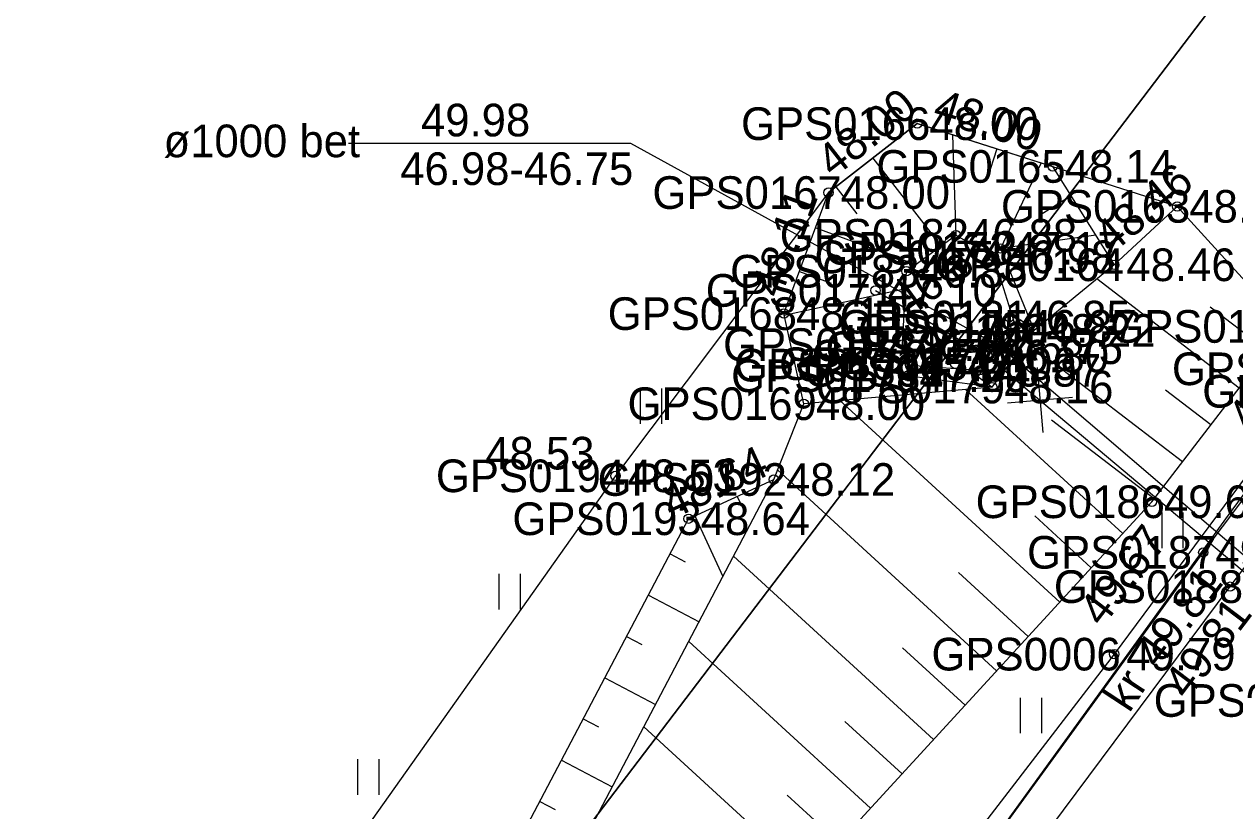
# Model space of a CAD drawing. Extents: x 563121 to 567545, y 6570841 to 6581299.
# Drawn here: x 565796.21 to 565822.17, y 6571860.9 to 6571877.77 of the extents above; entities that cross this region are included whole.
import ezdxf

# ---------------------------------------------------------------- set-up
doc = ezdxf.new("R2010")
doc.units = 0
for name, color, linetype in [('HALJASTUS', 7, 'Continuous'), ('KORGUS-EH2000', 7, 'Continuous'), ('MOOTKORG-EH2000', 7, 'Continuous'), ('MOOTMPUNKT', 7, 'Continuous'), ('MOOTNR', 7, 'Continuous'), ('MOOTPIIR', 7, 'Continuous'), ('PIIR', 7, 'Continuous'), ('RELJEEF', 7, 'Continuous'), ('SITRASS', 7, 'Continuous'), ('TEE', 7, 'Continuous'), ('TRUUP', 7, 'Continuous')]:
    doc.layers.add(name, color=color, linetype=linetype)

msp = doc.modelspace()

# ---------------------------------------------------------------- linework, layer by layer
at = {"layer": 'HALJASTUS'}
for p, q in [((565809.42, 6571869.956), (565809.42, 6571869.195)), ((565809.875, 6571869.956), (565809.875, 6571869.195)), ((565820.607, 6571867.295), (565820.607, 6571866.533)), ((565821.062, 6571867.295), (565821.062, 6571866.533)), ((565806.389, 6571865.979), (565806.389, 6571865.218)), ((565806.844, 6571865.979), (565806.844, 6571865.218)), ((565817.572, 6571863.321), (565817.572, 6571862.56)), ((565818.027, 6571863.321), (565818.027, 6571862.56)), ((565803.358, 6571862.003), (565803.358, 6571861.242)), ((565803.813, 6571862.003), (565803.813, 6571861.242))]:
    msp.add_line(p, q, dxfattribs=at)
at = {"layer": 'KORGUS-EH2000'}
for centre in [(565815.364, 6571875.639), (565818.268, 6571874.721), (565813.463, 6571874.16), (565819.589, 6571872.611), (565815.131, 6571872.472), (565812.505, 6571871.563), (565808.89, 6571868.083), (565820.396, 6571867.526), (565810.46, 6571867.163), (565821.499, 6571866.441), (565822.074, 6571865.705)]:
    msp.add_circle(centre, 0.1, dxfattribs=at)
at = {"layer": 'MOOTMPUNKT'}
for centre in [(565815.364, 6571875.639), (565818.268, 6571874.721), (565813.463, 6571874.16), (565820.939, 6571873.864), (565816.193, 6571873.244), (565817.007, 6571872.781), (565817.149, 6571872.963), (565819.589, 6571872.611), (565815.131, 6571872.472), (565814.466, 6571872.061), (565812.505, 6571871.563), (565817.339, 6571871.488), (565817.469, 6571871.291), (565817.872, 6571871.202), (565815.049, 6571870.898), (565817.174, 6571870.831), (565815.213, 6571870.458), (565816.178, 6571870.488), (565816.874, 6571870.651), (565815.151, 6571870.23), (565816.705, 6571870.347), (565816.969, 6571869.988), (565812.929, 6571869.63), (565808.89, 6571868.083), (565812.288, 6571868.004), (565820.396, 6571867.526), (565810.46, 6571867.163), (565821.499, 6571866.441), (565822.074, 6571865.705), (565819.589, 6571864.258)]:
    msp.add_circle(centre, 0.1, dxfattribs=at)
at = {"layer": 'MOOTPIIR'}
msp.add_lwpolyline([(565823.283, 6571871.288), (565820.939, 6571873.864), (565815.364, 6571875.639), (565813.463, 6571874.16), (565808.89, 6571868.083), (565802.021, 6571858.377), (565795.67, 6571849.773), (565782.207, 6571833.008), (565776.308, 6571825.832), (565781.278, 6571820.922), (565782.262, 6571820.691), (565783.542, 6571819.443), (565784.347, 6571818.115), (565785.017, 6571817.401), (565789.374, 6571812.429), (565790.175, 6571811.534), (565801.221, 6571799.668)], dxfattribs=at)
at = {"layer": 'PIIR'}
msp.add_lwpolyline([(564959.63, 6571567.88), (565247.22, 6571575.87), (565310, 6571592), (565385.09, 6571617.94), (565603.34, 6571696.36), (565663.71, 6571724.88), (565720.01, 6571762.52), (565767.05, 6571806.3), (565831.51, 6571891.07), (565894.85, 6571978.6), (565929.68, 6572026.82), (566028.25, 6572163.26), (566043.71, 6572184.75), (566068.58, 6572219.3), (566114.67, 6572283.35)], dxfattribs=at)
msp.add_lwpolyline([(565385.09, 6571617.94), (565348.3, 6571706.93), (565808.88, 6572174.3), (565817.95, 6572187.54), (565914.67, 6572223.63), (565927.34, 6572201.79), (566013.66, 6572213.36), (566028.25, 6572163.26), (565929.68, 6572026.82), (565869.35, 6572071.5), (565833.75, 6572019.48), (565773.79, 6571931.89), (565831.51, 6571891.07), (565767.05, 6571806.3), (565720.01, 6571762.52), (565663.71, 6571724.88), (565603.34, 6571696.36)], close=True, dxfattribs=at)
at = {"layer": 'RELJEEF'}
for p, q in [((565816.117, 6571875.401), (565816.193, 6571873.244)), ((565817.07, 6571875.1), (565816.866, 6571874.453)), ((565814.409, 6571874.896), (565815.875, 6571873.013)), ((565818.024, 6571874.798), (565817.149, 6571872.963)), ((565813.62, 6571874.281), (565814.071, 6571873.702)), ((565818.663, 6571874.091), (565818.019, 6571873.688)), ((565819.589, 6571872.611), (565820.939, 6571873.864)), ((565813.186, 6571873.407), (565815.33, 6571872.616)), ((565819.194, 6571873.243), (565817.149, 6571872.963)), ((565812.839, 6571872.469), (565813.514, 6571872.22)), ((565812.512, 6571871.53), (565815.111, 6571872.1)), ((565822.269, 6571869.967), (565819.219, 6571872.307)), ((565822.878, 6571870.76), (565821.648, 6571871.704)), ((565821.051, 6571868.38), (565817.691, 6571870.959)), ((565812.727, 6571870.553), (565813.426, 6571870.707)), ((565815.972, 6571869.899), (565815.954, 6571870.105)), ((565819.772, 6571866.846), (565816.402, 6571869.937)), ((565821.66, 6571869.174), (565820.69, 6571869.918)), ((565818.419, 6571865.372), (565813.704, 6571869.699)), ((565820.442, 6571867.587), (565818.244, 6571869.274)), ((565817.067, 6571863.898), (565812.369, 6571868.209)), ((565811.501, 6571867.642), (565811.584, 6571867.46)), ((565810.593, 6571867.224), (565811.193, 6571865.92)), ((565819.096, 6571866.109), (565817.883, 6571867.222)), ((565810.062, 6571866.407), (565810.388, 6571866.236)), ((565815.715, 6571862.425), (565811.424, 6571866.361)), ((565817.743, 6571864.635), (565816.249, 6571866.006)), ((565809.597, 6571865.522), (565810.683, 6571864.95)), ((565809.131, 6571864.637), (565809.457, 6571864.465)), ((565814.363, 6571860.951), (565810.462, 6571864.53)), ((565816.391, 6571863.162), (565815.046, 6571864.396)), ((565808.666, 6571863.752), (565809.753, 6571863.18)), ((565808.2, 6571862.867), (565808.527, 6571862.695)), ((565815.039, 6571861.688), (565813.81, 6571862.815)), ((565813.011, 6571859.477), (565809.5, 6571862.699)), ((565807.735, 6571861.982), (565808.823, 6571861.409)), ((565813.687, 6571860.214), (565812.575, 6571861.234)), ((565807.269, 6571861.097), (565807.596, 6571860.925))]:
    msp.add_line(p, q, dxfattribs=at)
for points in [[(565816.969, 6571869.988), (565812.929, 6571869.63), (565812.505, 6571871.563), (565813.463, 6571874.16), (565815.364, 6571875.639), (565818.268, 6571874.721), (565819.589, 6571872.611), (565817.872, 6571871.202)], [(565815.213, 6571870.458), (565815.049, 6571870.898), (565815.131, 6571872.472), (565816.193, 6571873.244), (565817.007, 6571872.781)], [(565800.51, 6571847.744), (565800.538, 6571847.723), (565801.66, 6571847.165), (565807.743, 6571853.735), (565820.396, 6571867.526), (565823.283, 6571871.288)], [(565800.861, 6571849.149), (565805.762, 6571855.585), (565812.288, 6571868.004), (565812.929, 6571869.63)], [(565799.345, 6571848.635), (565799.323, 6571848.653), (565799.23, 6571849.388), (565804.852, 6571856.501), (565810.46, 6571867.163), (565812.288, 6571868.004)]]:
    msp.add_lwpolyline(points, dxfattribs=at)
at = {"layer": 'SITRASS'}
for p, q in [((565817.933, 6571870.408), (565818.054, 6571869.013)), ((565817.296, 6571869.65), (565818.691, 6571869.771))]:
    msp.add_line(p, q, dxfattribs=at)
for points in [[(565827.937, 6571875.522), (565819.589, 6571864.258), (565813.931, 6571856.898), (565805.842, 6571846.363), (565798.797, 6571837.231), (565791.619, 6571827.726), (565784.171, 6571818.664)], [(565814.466, 6571872.061), (565816.874, 6571870.651), (565833.216, 6571856.912), (565834.731, 6571854.328)], [(565783.542, 6571819.443), (565787.788, 6571824.729), (565795.262, 6571834.475), (565801.765, 6571842.375), (565808.482, 6571851.414), (565811.284, 6571854.993), (565814.22, 6571858.353), (565815.357, 6571859.794), (565816.36, 6571859.39), (565822.04, 6571867.24), (565823.485, 6571869.196), (565824.591, 6571870.729)]]:
    msp.add_lwpolyline(points, dxfattribs=at)
at = {"layer": 'TEE'}
for points in [[(565784.347, 6571818.115), (565798.874, 6571835.854), (565810.584, 6571851.423), (565821.499, 6571866.441), (565824.465, 6571870.379)], [(565785.017, 6571817.401), (565799.254, 6571835.472), (565811.058, 6571850.919), (565822.074, 6571865.705), (565825.255, 6571869.896)]]:
    msp.add_lwpolyline(points, dxfattribs=at)
at = {"layer": 'TRUUP'}
for p, q in [((565817.019, 6571871.556), (565817.161, 6571871.567)), ((565817.068, 6571870.922), (565817.019, 6571871.556)), ((565817.02, 6571871.55), (565817.167, 6571871.489)), ((565817.022, 6571871.522), (565817.17, 6571871.462)), ((565817.024, 6571871.494), (565817.172, 6571871.434)), ((565817.026, 6571871.466), (565817.174, 6571871.406)), ((565817.029, 6571871.438), (565817.176, 6571871.378)), ((565817.031, 6571871.411), (565817.178, 6571871.35)), ((565817.033, 6571871.383), (565817.18, 6571871.322)), ((565817.035, 6571871.355), (565817.182, 6571871.294)), ((565817.037, 6571871.327), (565817.185, 6571871.266)), ((565817.064, 6571871.559), (565817.165, 6571871.517)), ((565817.145, 6571870.856), (565817.09, 6571871.561)), ((565817.119, 6571871.563), (565817.163, 6571871.545)), ((565817.221, 6571870.791), (565817.161, 6571871.567)), ((565817.039, 6571871.299), (565817.187, 6571871.238)), ((565817.041, 6571871.271), (565817.189, 6571871.21)), ((565817.044, 6571871.243), (565817.191, 6571871.182)), ((565817.046, 6571871.215), (565817.193, 6571871.155)), ((565817.048, 6571871.187), (565817.195, 6571871.127)), ((565817.05, 6571871.159), (565817.197, 6571871.099)), ((565817.052, 6571871.131), (565817.2, 6571871.071)), ((565817.054, 6571871.103), (565817.202, 6571871.043)), ((565817.056, 6571871.076), (565817.204, 6571871.015)), ((565816.434, 6571870.873), (565817.068, 6571870.922)), ((565816.434, 6571870.873), (565816.445, 6571870.731)), ((565816.434, 6571870.872), (565816.725, 6571870.752)), ((565816.437, 6571870.844), (565816.67, 6571870.748)), ((565816.439, 6571870.816), (565816.614, 6571870.744)), ((565816.44, 6571870.802), (565817.145, 6571870.856)), ((565816.488, 6571870.877), (565816.78, 6571870.757)), ((565816.543, 6571870.881), (565816.836, 6571870.761)), ((565816.598, 6571870.885), (565816.891, 6571870.765)), ((565816.654, 6571870.89), (565816.947, 6571870.769)), ((565816.709, 6571870.894), (565817.002, 6571870.774)), ((565816.765, 6571870.898), (565817.057, 6571870.778)), ((565816.82, 6571870.902), (565817.113, 6571870.782)), ((565816.875, 6571870.907), (565817.168, 6571870.786)), ((565816.931, 6571870.911), (565817.221, 6571870.792)), ((565816.986, 6571870.915), (565817.219, 6571870.82)), ((565817.042, 6571870.92), (565817.217, 6571870.848)), ((565817.059, 6571871.048), (565817.206, 6571870.987)), ((565817.061, 6571871.02), (565817.208, 6571870.959)), ((565817.063, 6571870.992), (565817.21, 6571870.931)), ((565817.065, 6571870.964), (565817.213, 6571870.903)), ((565817.067, 6571870.936), (565817.215, 6571870.875)), ((565817.145, 6571870.856), (565833.415, 6571856.915)), ((565816.441, 6571870.788), (565816.559, 6571870.739)), ((565816.443, 6571870.76), (565816.503, 6571870.735)), ((565816.445, 6571870.731), (565817.221, 6571870.791))]:
    msp.add_line(p, q, dxfattribs=at)
for points in [[(565817.145, 6571870.856), (565809.223, 6571875.215), (565803.165, 6571875.215)], [(565817.469, 6571871.291), (565817.007, 6571872.781), (565817.149, 6571872.963), (565817.872, 6571871.202)], [(565816.969, 6571869.988), (565815.151, 6571870.23), (565815.213, 6571870.458), (565816.763, 6571870.342)]]:
    msp.add_lwpolyline(points, dxfattribs=at)
msp.add_lwpolyline([(565816.969, 6571869.988), (565817.872, 6571871.202), (565817.57, 6571871.427), (565816.666, 6571870.213)], close=True, dxfattribs=at)

# ---------------------------------------------------------------- texts
at = {"layer": 'KORGUS-EH2000'}
for s, rotation, p in [(' 48.00', 37.9002, (565813.356, 6571874.298)), (' 48.00', 342.4462, (565815.417, 6571875.806)), (' 48.46', 39.3796, (565819.325, 6571872.655)), (' 48.11', 69.7415, (565812.341, 6571871.624)), (' 46.86', 36.0123, (565814.956, 6571871.296)), (' 49.65', 52.4986, (565822.368, 6571868.773)), (' 48.64', 24.726, (565809.86, 6571867.03)), (' 49.67', 52.4986, (565819.176, 6571864.607)), (' 49.81', 53.0097, (565820.385, 6571863.702)), (' 49.81', 52.8026, (565821, 6571863.045))]:
    msp.add_text(s, height=0.7, rotation=rotation, dxfattribs=at).set_placement(p)
msp.add_text(' 48.53', height=0.7, dxfattribs=at).set_placement((565805.838, 6571868.219))
at = {"layer": 'MOOTKORG-EH2000'}
for s, p in [(' 48.00', (565815.364, 6571875.289)), (' 48.14', (565818.268, 6571874.371)), (' 48.00', (565813.463, 6571873.81)), (' 48.55', (565820.939, 6571873.514)), (' 46.88', (565816.193, 6571872.894)), (' 46.98', (565817.007, 6571872.431)), (' 47.17', (565817.149, 6571872.613)), (' 48.46', (565819.589, 6571872.261)), (' 46.86', (565815.131, 6571872.122)), (' 47.10', (565814.466, 6571871.711)), (' 48.11', (565812.505, 6571871.213)), (' 46.85', (565817.339, 6571871.138)), (' 46.87', (565817.469, 6571870.941)), (' 48.22', (565817.872, 6571870.852)), (' 46.94', (565815.049, 6571870.548)), (' 46.75', (565817.174, 6571870.481)), (' 47.01', (565815.213, 6571870.108)), (' 47.06', (565816.178, 6571870.138)), (' 46.80', (565816.874, 6571870.301)), (' 47.29', (565815.151, 6571869.88)), (' 46.87', (565816.705, 6571869.997)), (' 48.16', (565816.969, 6571869.638)), (' 48.00', (565812.929, 6571869.28)), (' 48.53', (565808.89, 6571867.733)), (' 48.12', (565812.288, 6571867.654)), (' 49.67', (565820.396, 6571867.176)), (' 48.64', (565810.46, 6571866.812)), (' 49.81', (565821.499, 6571866.091)), (' 49.79', (565819.589, 6571863.907))]:
    msp.add_text(s, height=0.7, dxfattribs=at).set_placement(p)
at = {"layer": 'MOOTNR'}
for s, p in [('GPS0166 ', (565811.585, 6571875.289)), ('GPS0165 ', (565814.488, 6571874.371)), ('GPS0167 ', (565809.684, 6571873.81)), ('GPS0163 ', (565817.159, 6571873.514)), ('GPS0182 ', (565812.414, 6571872.894)), ('GPS0174 ', (565813.158, 6571872.431)), ('GPS0173 ', (565813.369, 6571872.613)), ('GPS0164 ', (565815.74, 6571872.261)), ('GPS0183 ', (565811.351, 6571872.122)), ('GPS0171 ', (565810.827, 6571871.711)), ('GPS0168 ', (565808.725, 6571871.213)), ('GPS0181 ', (565813.7, 6571871.138)), ('GPS0175 ', (565813.689, 6571870.941)), ('GPS0162 ', (565819.503, 6571870.938)), ('GPS0180 ', (565814.092, 6571870.852)), ('GPS0184 ', (565811.199, 6571870.548)), ('GPS0172 ', (565813.395, 6571870.481)), ('GPS0177 ', (565811.433, 6571870.108)), ('GPS0185 ', (565812.398, 6571870.138)), ('GPS0170 ', (565813.095, 6571870.301)), ('GPS0178 ', (565811.372, 6571869.88)), ('GPS0176 ', (565812.925, 6571869.997)), ('GPS0161 ', (565820.826, 6571870.029)), ('GPS0179 ', (565813.189, 6571869.638)), ('GPS0160 ', (565821.476, 6571869.547)), ('GPS0169 ', (565809.15, 6571869.28)), ('GPS0194 ', (565805.04, 6571867.733)), ('GPS0192 ', (565808.508, 6571867.654)), ('GPS0186 ', (565816.616, 6571867.176)), ('GPS0193 ', (565806.68, 6571866.812)), ('GPS0187 ', (565817.719, 6571866.091)), ('GPS0188 ', (565818.294, 6571865.355)), ('GPS0006 ', (565815.669, 6571863.907)), ('GPS0189 ', (565820.435, 6571862.913))]:
    msp.add_text(s, height=0.7, dxfattribs=at).set_placement(p)
at = {"layer": 'TEE'}
msp.add_text('kr', height=0.7, rotation=56.7555, dxfattribs=at).set_placement((565819.912, 6571862.977))
at = {"layer": 'TRUUP'}
for s, p in [('49.98', (565804.72, 6571875.366)), ('ø1000 bet', (565799.198, 6571874.919)), ('46.98-46.75', (565804.275, 6571874.323))]:
    msp.add_text(s, height=0.7, dxfattribs=at).set_placement(p)

doc.saveas('drawing.dxf')
